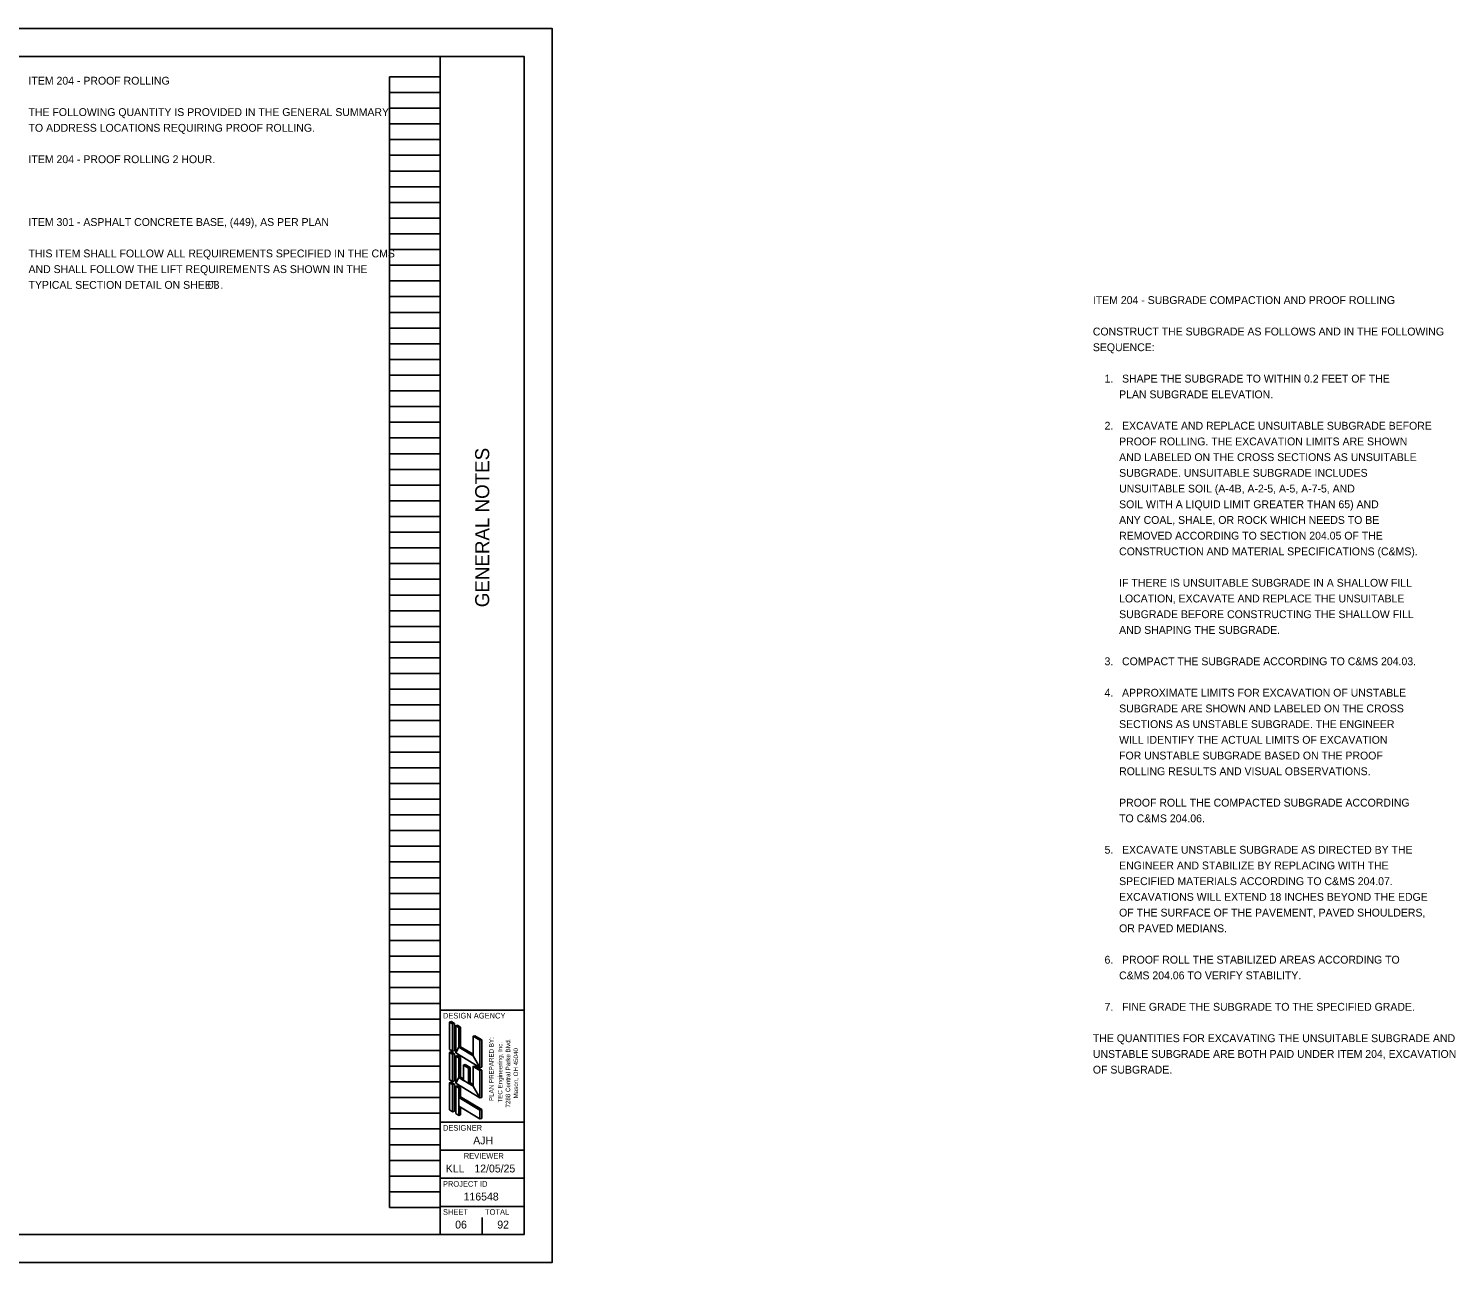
# Model space of a CAD drawing. Extents: x 0 to 50.1, y 0 to 22.
# Drawn here: x 24.66 to 50.11, y 0 to 22 of the extents above; entities that cross this region are included whole.
import ezdxf

# ---------------------------------------------------------------- set-up
doc = ezdxf.new("R2010")
doc.units = 0
for name, color, linetype in [('Default', 7, 'Continuous'), ('SH_Border', 7, 'Continuous'), ('SH_Cut_Line', 7, 'Continuous'), ('SH_Data', 7, 'Continuous'), ('SH_Text', 7, 'Continuous')]:
    doc.layers.add(name, color=color, linetype=linetype)

msp = doc.modelspace()

# ---------------------------------------------------------------- linework, layer by layer
at = {"layer": 'SH_Border'}
for p, q in [((32, 0.5), (32, 21.5)), ((32, 4.5), (33.5, 4.5)), ((32, 2.5), (33.5, 2.5)), ((32, 2), (33.5, 2)), ((32, 1.5), (33.5, 1.5)), ((32, 1), (33.5, 1))]:
    msp.add_line(p, q, dxfattribs=at)
msp.add_lwpolyline([(1.5, 21.5), (33.5, 21.5), (33.5, 0.5), (1.5, 0.5)], close=True, dxfattribs=at)
at = {"layer": 'SH_Cut_Line'}
msp.add_lwpolyline([(0, 0), (34, 0), (34, 22), (0, 22)], close=True, dxfattribs=at)
at = {"layer": 'SH_Data'}
for p, q in [((31.1, 0.98), (31.1, 21.14)), ((31.1, 21.14), (32, 21.14)), ((32, 0.98), (32, 21.14)), ((31.1, 20.86), (32, 20.86)), ((31.1, 20.58), (32, 20.58)), ((31.1, 20.3), (32, 20.3)), ((31.1, 20.02), (32, 20.02)), ((31.1, 19.74), (32, 19.74)), ((31.1, 19.46), (32, 19.46)), ((31.1, 19.18), (32, 19.18)), ((31.1, 18.9), (32, 18.9)), ((31.1, 18.62), (32, 18.62)), ((31.1, 18.34), (32, 18.34)), ((31.1, 18.06), (32, 18.06)), ((31.1, 17.78), (32, 17.78)), ((31.1, 17.5), (32, 17.5)), ((31.1, 17.22), (32, 17.22)), ((31.1, 16.94), (32, 16.94)), ((31.1, 16.66), (32, 16.66)), ((31.1, 16.38), (32, 16.38)), ((31.1, 16.1), (32, 16.1)), ((31.1, 15.82), (32, 15.82)), ((31.1, 15.54), (32, 15.54)), ((31.1, 15.26), (32, 15.26)), ((31.1, 14.98), (32, 14.98)), ((31.1, 14.7), (32, 14.7)), ((31.1, 14.42), (32, 14.42)), ((31.1, 14.14), (32, 14.14)), ((31.1, 13.86), (32, 13.86)), ((31.1, 13.58), (32, 13.58)), ((31.1, 13.3), (32, 13.3)), ((31.1, 13.02), (32, 13.02)), ((31.1, 12.74), (32, 12.74)), ((31.1, 12.46), (32, 12.46)), ((31.1, 12.18), (32, 12.18)), ((31.1, 11.9), (32, 11.9)), ((31.1, 11.62), (32, 11.62)), ((31.1, 11.34), (32, 11.34)), ((31.1, 11.06), (32, 11.06)), ((31.1, 10.78), (32, 10.78)), ((31.1, 10.5), (32, 10.5)), ((31.1, 10.22), (32, 10.22)), ((31.1, 9.94), (32, 9.94)), ((31.1, 9.66), (32, 9.66)), ((31.1, 9.38), (32, 9.38)), ((31.1, 9.1), (32, 9.1)), ((31.1, 8.82), (32, 8.82)), ((31.1, 8.54), (32, 8.54)), ((31.1, 8.26), (32, 8.26)), ((31.1, 7.98), (32, 7.98)), ((31.1, 7.7), (32, 7.7)), ((31.1, 7.42), (32, 7.42)), ((31.1, 7.14), (32, 7.14)), ((31.1, 6.86), (32, 6.86)), ((31.1, 6.58), (32, 6.58)), ((31.1, 6.3), (32, 6.3)), ((31.1, 6.02), (32, 6.02)), ((31.1, 5.74), (32, 5.74)), ((31.1, 5.46), (32, 5.46)), ((31.1, 5.18), (32, 5.18)), ((31.1, 4.9), (32, 4.9)), ((31.1, 4.62), (32, 4.62)), ((31.1, 4.34), (32, 4.34)), ((31.1, 4.06), (32, 4.06)), ((31.1, 3.78), (32, 3.78)), ((31.1, 3.5), (32, 3.5)), ((32.75, 3.5), (32.75, 3.5)), ((31.1, 3.22), (32, 3.22)), ((31.1, 2.94), (32, 2.94)), ((31.1, 2.66), (32, 2.66)), ((31.1, 2.38), (32, 2.38)), ((31.1, 2.1), (32, 2.1)), ((31.1, 1.82), (32, 1.82)), ((31.1, 1.54), (32, 1.54)), ((31.1, 1.26), (32, 1.26)), ((31.1, 0.98), (32, 0.98)), ((32.75, 0.5), (32.75, 0.8)), ((32.375, 0.675), (32.375, 0.675))]:
    msp.add_line(p, q, dxfattribs=at)
at = {"layer": 'SH_Text'}
for p, q in [((32.169, 4.285), (32.201, 4.294)), ((32.169, 3.799), (32.169, 4.285)), ((32.223, 4.253), (32.169, 4.285)), ((32.255, 4.261), (32.201, 4.294)), ((32.223, 4.253), (32.255, 4.261)), ((32.223, 3.767), (32.223, 4.253)), ((32.255, 3.775), (32.255, 4.261)), ((32.277, 4.221), (32.309, 4.229)), ((32.331, 4.188), (32.277, 4.221)), ((32.277, 3.735), (32.277, 4.221)), ((32.309, 4.229), (32.363, 4.196)), ((32.331, 4.188), (32.363, 4.196)), ((32.331, 3.837), (32.331, 4.188)), ((32.363, 4.196), (32.363, 3.845)), ((32.331, 3.837), (32.363, 3.845)), ((32.587, 3.683), (32.331, 3.837)), ((32.363, 3.845), (32.587, 3.711)), ((32.587, 4.034), (32.62, 4.042)), ((32.587, 3.683), (32.587, 4.034)), ((32.709, 3.961), (32.587, 4.034)), ((32.62, 4.042), (32.741, 3.97)), ((32.709, 3.961), (32.741, 3.97)), ((32.709, 3.475), (32.709, 3.961)), ((32.741, 3.97), (32.741, 3.484)), ((32.223, 3.767), (32.169, 3.799)), ((32.169, 3.745), (32.201, 3.754)), ((32.169, 3.259), (32.169, 3.745)), ((32.223, 3.713), (32.169, 3.745)), ((32.255, 3.722), (32.201, 3.754)), ((32.223, 3.767), (32.255, 3.775)), ((32.223, 3.713), (32.255, 3.722)), ((32.223, 3.227), (32.223, 3.713)), ((32.255, 3.236), (32.255, 3.722)), ((32.709, 3.475), (32.277, 3.735)), ((32.277, 3.681), (32.309, 3.689)), ((32.277, 3.195), (32.277, 3.681)), ((32.331, 3.648), (32.277, 3.681)), ((32.309, 3.689), (32.363, 3.656)), ((32.331, 3.648), (32.363, 3.656)), ((32.331, 3.297), (32.331, 3.648)), ((32.363, 3.656), (32.363, 3.305)), ((32.415, 3.519), (32.448, 3.527)), ((32.415, 3.519), (32.415, 3.247)), ((32.415, 3.519), (32.503, 3.466)), ((32.448, 3.527), (32.535, 3.474)), ((32.503, 3.466), (32.535, 3.474)), ((32.503, 3.466), (32.503, 3.194)), ((32.535, 3.474), (32.535, 3.202)), ((32.587, 3.494), (32.62, 3.502)), ((32.587, 3.143), (32.587, 3.494)), ((32.709, 3.421), (32.587, 3.494)), ((32.62, 3.502), (32.741, 3.43)), ((32.709, 3.475), (32.741, 3.484)), ((32.709, 3.421), (32.741, 3.43)), ((32.709, 2.935), (32.709, 3.421)), ((32.741, 3.43), (32.741, 2.944)), ((32.223, 3.227), (32.169, 3.259)), ((32.169, 3.205), (32.201, 3.215)), ((32.169, 2.719), (32.169, 3.205)), ((32.223, 3.173), (32.169, 3.205)), ((32.255, 3.181), (32.201, 3.215)), ((32.222, 3.173), (32.255, 3.181)), ((32.223, 3.227), (32.255, 3.236)), ((32.223, 2.687), (32.223, 3.173)), ((32.255, 2.695), (32.255, 3.181)), ((32.709, 2.935), (32.277, 3.195)), ((32.277, 3.141), (32.309, 3.151)), ((32.331, 3.108), (32.277, 3.141)), ((32.277, 2.655), (32.277, 3.141)), ((32.309, 3.151), (32.363, 3.116)), ((32.331, 3.297), (32.363, 3.305)), ((32.415, 3.247), (32.331, 3.297)), ((32.331, 3.108), (32.363, 3.116)), ((32.331, 2.944), (32.331, 3.108)), ((32.363, 3.305), (32.415, 3.274)), ((32.363, 3.116), (32.363, 2.952)), ((32.503, 3.194), (32.535, 3.202)), ((32.587, 3.143), (32.503, 3.194)), ((32.535, 3.202), (32.587, 3.171)), ((32.331, 2.944), (32.363, 2.952)), ((32.331, 2.944), (32.709, 2.717)), ((32.363, 2.952), (32.741, 2.725)), ((32.709, 2.935), (32.741, 2.944)), ((32.223, 2.687), (32.169, 2.719)), ((32.223, 2.687), (32.255, 2.695)), ((32.331, 2.622), (32.277, 2.655)), ((32.331, 2.787), (32.709, 2.56)), ((32.331, 2.622), (32.331, 2.787)), ((32.331, 2.622), (32.363, 2.63)), ((32.363, 2.63), (32.363, 2.767)), ((32.709, 2.717), (32.741, 2.725)), ((32.709, 2.56), (32.709, 2.717)), ((32.709, 2.56), (32.741, 2.568)), ((32.741, 2.725), (32.741, 2.568))]:
    msp.add_line(p, q, dxfattribs=at)
for points in [[(32.169, 3.799), (32.223, 3.767), (32.223, 4.253), (32.169, 4.285)], [(32.277, 3.735), (32.331, 3.837), (32.331, 4.188), (32.277, 4.221)], [(32.277, 3.735), (32.331, 3.837), (32.587, 3.683), (32.709, 3.475)], [(32.709, 3.475), (32.587, 3.683), (32.587, 4.034), (32.709, 3.961)], [(32.169, 3.259), (32.223, 3.227), (32.223, 3.713), (32.169, 3.745)], [(32.277, 3.195), (32.331, 3.297), (32.331, 3.648), (32.277, 3.681)], [(32.415, 3.247), (32.415, 3.519), (32.503, 3.466), (32.503, 3.194)], [(32.709, 2.935), (32.587, 3.143), (32.587, 3.494), (32.709, 3.421)], [(32.169, 2.719), (32.223, 2.687), (32.223, 3.173), (32.169, 3.205)], [(32.277, 3.195), (32.331, 3.297), (32.587, 3.143), (32.709, 2.935)], [(32.277, 2.655), (32.331, 2.622), (32.331, 3.108), (32.277, 3.141)], [(32.331, 2.787), (32.331, 2.944), (32.709, 2.717), (32.709, 2.56)]]:
    msp.add_lwpolyline(points, close=True, dxfattribs=at)

# ---------------------------------------------------------------- texts
at = {"layer": 'Default'}
for s, p in [('PLAN PREPARED BY:', (32.954, 2.88)), ('TEC Engineering, Inc.', (33.11, 2.851)), ('7288 Central Parke Blvd.', (33.25, 2.762)), ('Mason, OH 45040', (33.39, 2.925))]:
    msp.add_text(s, height=0.08, rotation=90, dxfattribs=at).set_placement(p)
at = {"layer": 'SH_Data'}
msp.add_text('GENERAL NOTES', height=0.25, rotation=90, dxfattribs=at).set_placement((32.875, 11.682))
for s, height, p in [('DESIGN AGENCY', 0.1, (32.05, 4.35)), ('DESIGNER', 0.1, (32.05, 2.35)), ('AJH', 0.14, (32.59, 2.105)), ('REVIEWER', 0.1, (32.422, 1.85)), ('KLL', 0.14, (32.101, 1.605)), ('12/05/25', 0.14, (32.611, 1.605)), ('PROJECT ID', 0.1, (32.05, 1.35)), ('116548', 0.14, (32.419, 1.105)), ('SHEET', 0.1, (32.05, 0.85)), ('TOTAL', 0.1, (32.8, 0.85)), ('06', 0.14, (32.268, 0.605)), ('92', 0.14, (33.019, 0.605))]:
    msp.add_text(s, height=height, dxfattribs=at).set_placement(p)
at = {"layer": 'SH_Text'}
for s, p in [('ITEM 204 - PROOF ROLLING', (24.66, 21)), ('THE FOLLOWING QUANTITY IS PROVIDED IN THE GENERAL SUMMARY ', (24.66, 20.44)), ('TO ADDRESS LOCATIONS REQUIRING PROOF ROLLING. ', (24.66, 20.16)), ('ITEM 204 - PROOF ROLLING 2 HOUR.', (24.66, 19.6)), ('ITEM 301 - ASPHALT CONCRETE BASE, (449), AS PER PLAN', (24.66, 18.48)), ('THIS ITEM SHALL FOLLOW ALL REQUIREMENTS SPECIFIED IN THE CMS ', (24.66, 17.92)), ('AND SHALL FOLLOW THE LIFT REQUIREMENTS AS SHOWN IN THE ', (24.66, 17.64)), ('TYPICAL SECTION DETAIL ON SHEET', (24.66, 17.36)), ('03', (27.856, 17.36)), ('.', (28.08, 17.36)), ('ITEM 204 - SUBGRADE COMPACTION AND PROOF ROLLING', (43.64, 17.088)), ('CONSTRUCT THE SUBGRADE AS FOLLOWS AND IN THE FOLLOWING ', (43.64, 16.528)), ('SEQUENCE:', (43.64, 16.248)), ('    1.   SHAPE THE SUBGRADE TO WITHIN 0.2 FEET OF THE', (43.64, 15.688)), ('         PLAN SUBGRADE ELEVATION.', (43.64, 15.408)), ('    2.   EXCAVATE AND REPLACE UNSUITABLE SUBGRADE BEFORE', (43.64, 14.848)), ('         PROOF ROLLING. THE EXCAVATION LIMITS ARE SHOWN', (43.64, 14.568)), ('         AND LABELED ON THE CROSS SECTIONS AS UNSUITABLE', (43.64, 14.288)), ('         SUBGRADE. UNSUITABLE SUBGRADE INCLUDES', (43.64, 14.008)), ('         UNSUITABLE SOIL (A-4B, A-2-5, A-5, A-7-5, AND', (43.64, 13.728)), ('         SOIL WITH A LIQUID LIMIT GREATER THAN 65) AND', (43.64, 13.448)), ('         ANY COAL, SHALE, OR ROCK WHICH NEEDS TO BE', (43.64, 13.168)), ('         REMOVED ACCORDING TO SECTION 204.05 OF THE', (43.64, 12.888)), ('         CONSTRUCTION AND MATERIAL SPECIFICATIONS (C&MS).', (43.64, 12.608)), ('         IF THERE IS UNSUITABLE SUBGRADE IN A SHALLOW FILL', (43.64, 12.048)), ('         LOCATION, EXCAVATE AND REPLACE THE UNSUITABLE', (43.64, 11.768)), ('         SUBGRADE BEFORE CONSTRUCTING THE SHALLOW FILL', (43.64, 11.488)), ('         AND SHAPING THE SUBGRADE.', (43.64, 11.208)), ('    3.   COMPACT THE SUBGRADE ACCORDING TO C&MS 204.03.', (43.64, 10.648)), ('    4.   APPROXIMATE LIMITS FOR EXCAVATION OF UNSTABLE', (43.64, 10.088)), ('         SUBGRADE ARE SHOWN AND LABELED ON THE CROSS', (43.64, 9.808)), ('         SECTIONS AS UNSTABLE SUBGRADE. THE ENGINEER', (43.64, 9.528)), ('         WILL IDENTIFY THE ACTUAL LIMITS OF EXCAVATION', (43.64, 9.248)), ('         FOR UNSTABLE SUBGRADE BASED ON THE PROOF', (43.64, 8.968)), ('         ROLLING RESULTS AND VISUAL OBSERVATIONS.', (43.64, 8.688)), ('         PROOF ROLL THE COMPACTED SUBGRADE ACCORDING', (43.64, 8.128)), ('         TO C&MS 204.06.', (43.64, 7.848)), ('    5.   EXCAVATE UNSTABLE SUBGRADE AS DIRECTED BY THE', (43.64, 7.288)), ('         ENGINEER AND STABILIZE BY REPLACING WITH THE', (43.64, 7.008)), ('         SPECIFIED MATERIALS ACCORDING TO C&MS 204.07.', (43.64, 6.728)), ('         EXCAVATIONS WILL EXTEND 18 INCHES BEYOND THE EDGE', (43.64, 6.448)), ('         OF THE SURFACE OF THE PAVEMENT, PAVED SHOULDERS,', (43.64, 6.168)), ('         OR PAVED MEDIANS.', (43.64, 5.888)), ('    6.   PROOF ROLL THE STABILIZED AREAS ACCORDING TO', (43.64, 5.328)), ('         C&MS 204.06 TO VERIFY STABILITY.', (43.64, 5.048)), ('    7.   FINE GRADE THE SUBGRADE TO THE SPECIFIED GRADE.', (43.64, 4.488)), ('THE QUANTITIES FOR EXCAVATING THE UNSUITABLE SUBGRADE AND ', (43.64, 3.928)), ('UNSTABLE SUBGRADE ARE BOTH PAID UNDER ITEM 204, EXCAVATION ', (43.64, 3.648)), ('OF SUBGRADE.', (43.64, 3.368))]:
    msp.add_text(s, height=0.14, dxfattribs=at).set_placement(p)

doc.saveas('drawing.dxf')
